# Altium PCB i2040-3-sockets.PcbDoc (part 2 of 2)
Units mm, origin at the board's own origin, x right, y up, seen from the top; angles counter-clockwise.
Board outline 210 x 90 mm, 2 copper layers (Top Layer, Bottom Layer), stack 1.575 mm thick; 146 components, 88 nets, 453 pads, 125 vias.
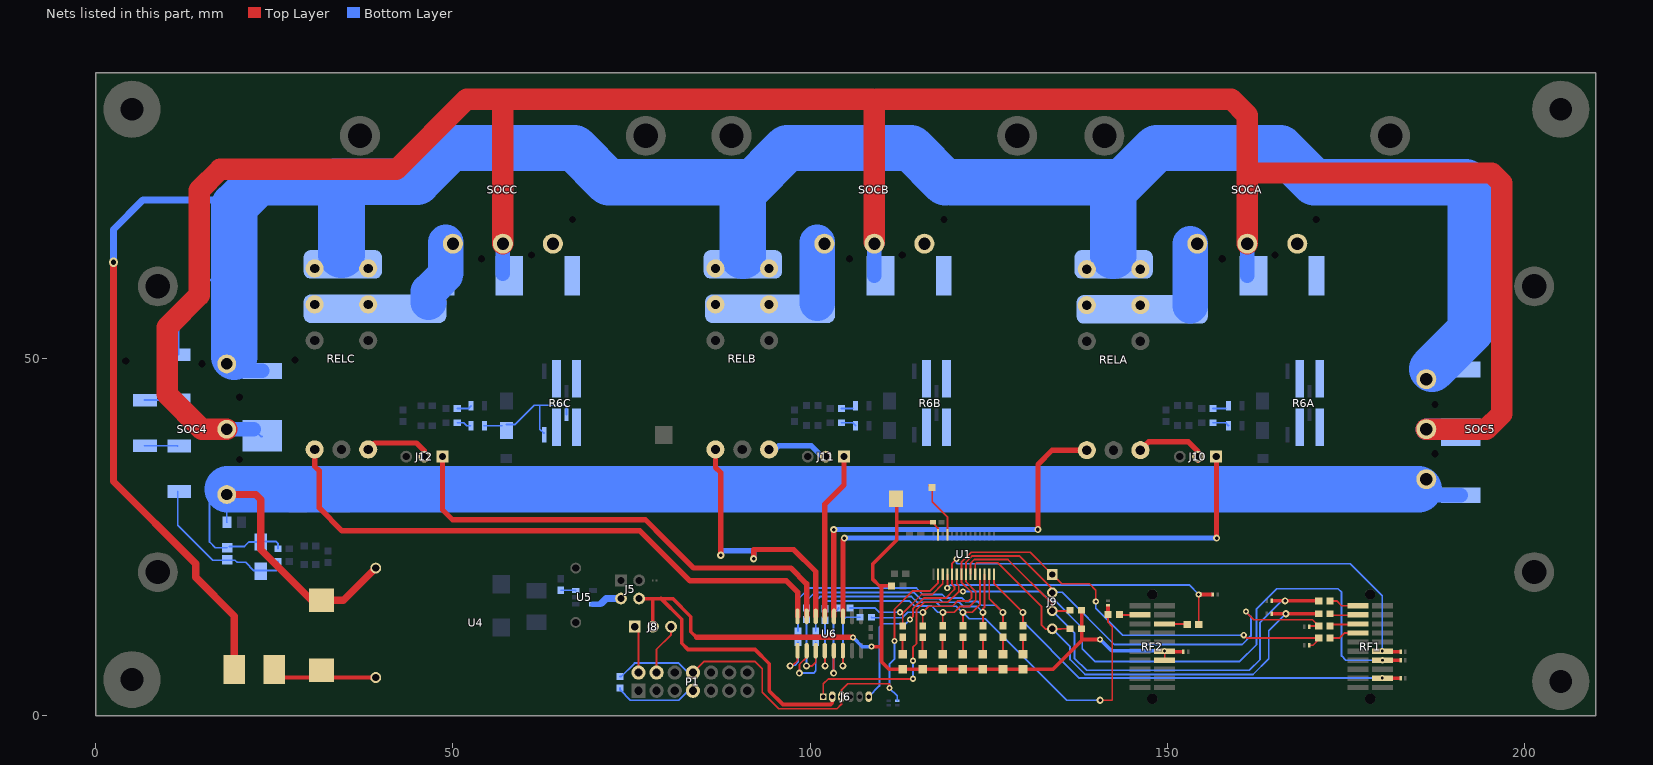
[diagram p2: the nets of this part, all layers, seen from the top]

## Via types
v1: diameter 1, hole 0.5, Top Layer to Bottom Layer, 44 vias
v2: diameter 0.864, hole 0.406, Top Layer to Bottom Layer, 40 vias
v3: diameter 1.27, hole 0.711, Top Layer to Bottom Layer, 40 vias
v4: diameter 0.864, hole 0.406, Top Layer to Bottom Layer, tented bottom, 1 vias

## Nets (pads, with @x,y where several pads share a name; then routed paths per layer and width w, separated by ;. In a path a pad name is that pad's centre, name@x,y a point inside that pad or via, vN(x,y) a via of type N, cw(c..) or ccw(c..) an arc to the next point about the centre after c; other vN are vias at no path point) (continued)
NetD1C_2: D1C.2 L1C.1 R6C.4 R6C.6 | length 17.4
  Bottom Layer w0.254: L1C.1@54.364,40.625 D1C.2@56.868,40.625 ; D1C.2@57.518,40.775 58.675,40.775 61.4,43.5 62.17,43.5 62.17,40.13 62.7,39.6 R6C.6@62.8,39.6 ; 62.2,43.5 65.7,43.5 65.9,43.3 R6C.4@65.9,42.15
NetD2A_1: D2A.1 D2B.1 D2C.1 D3A.1 D3B.1 D3C.1 D9.1 D10.1 D11.1 D12.2 SOC4.3 SOC5.3 SOCA.3 SOCB.3 SOCC.3 | length 355.5
  Top Layer w0.254: 108.638,86.344 109,85.982 109.362,86.344
  Top Layer w3: SOC4.3@18.35,40.132 14.868,40.132 10,45 10,54.413 14.5,58.913 14.5,73.6 17.4,76.5 42.1,76.5 51.944,86.344 108.638,86.344 ; SOCC.3@57,66.1 57,86.3 ; SOCB.3@109,66.278 109,85.982 ; 109.362,86.344 158.956,86.344 161.2,84.1 161.2,76 ; SOCA.3@161.2,66.1 161.2,76 ; SOC5.3@186.258,40.132 194.668,40.132 196.8,42.264 196.8,74.6 195.4,76 161.2,76
  Bottom Layer w0.254: D10.1@22.132,40.132 23.164,39.1 D9.1@23.3,39.1 ; D11.1@190.732,40.132 D11.1@191.1,40.5
  Bottom Layer w2: SOC4.3@18.35,40.132 D10.1@22.132,40.132 ; D3C.1@57,61.9 SOCC.3@57,66.1 ; D3B.1@109,61.6 SOCB.3@109,66.1 ; D3A.1@161.2,61.6 SOCA.3@161.2,66.1
  Bottom Layer w3: SOC5.3@186.258,40.132 D11.1@190.732,40.132
NetD2A_2: D2A.2 R6A.1 SOCA.2
NetD2B_2: D2B.2 R6B.1 SOCB.2
NetD2C_2: D2C.2 R6C.1 SOCC.2
NetD3A_2: D3A.2 pad.0@146.5,56.9 RELA.5 RELA.6 SOCA.1 | length 8.7
  Bottom Layer w5: pad.0@153.2,57.4 SOCA.1@153.2,66.1
NetD3B_2: D3B.2 pad.0@94.4,57 RELB.5 RELB.6 SOCB.1 | length 8.5
  Bottom Layer w5: pad.0@101,57.8 SOCB.1@101,66.3
NetD3C_2: D3C.2 pad.0@39.1,57 RELC.5 RELC.6 SOCC.1 | length 9.4
  Bottom Layer w5: pad.0@46.6,57.9 46.6,59.4 48.9,61.7 48.9,61.9 49,62 SOCC.1@49,66.3
NetD6_1: D6.1 FR.1 U4.2 | length 12.6
  Top Layer w0.254: FR.1@25,5.3 FR.1@25.076,5.376 ; D6.1@31.6,5.4 D6.1@31.624,5.376
  Top Layer w0.5: FR.1@25.076,5.376 D6.1@30,5.376 ; D6.1@31.624,5.376 U4.2@39.2,5.376
NetD6_2: D6.2 D8.1 D9.2 D12.1 R6A.2 R6B.2 R6C.2 R11.1 R15.1 R55.2 R56.2 R57.2 R58.2 SOC4.2 SOC5.2 U4.1 | length 228.7
  Top Layer w1: SOC4.2@18.35,30.992 22.408,30.992 23.1,30.3 23.1,23.3 31.2,15.2 31.2,15.8 D6.2@31.6,16.2 34.7,16.2 U4.1@39.2,20.7
  Bottom Layer w0.254: 15.95,31.092 15.95,24.35 16.75,23.55 R15.1@18.4,23.55 ; SOC4.2@18.35,30.992 18.35,27.134 R58.2@18.384,27.1 ; R15.1@18.74,23.716 20.816,23.716 21.45,24.35 D8.1@23.1,24.35 ; D8.1@23.195,24.416 23.199,24.42 25.262,24.402 25.507,24.153 R11.1@25.5,23.4 ; 185.2,31.2 185.5,30.9
  Bottom Layer w2: 184.9,30.9 D12.1@191.1,30.9
  Bottom Layer w6.5: SOC4.2@18.45,31.7 185.2,31.7
NetD8_2: D8.2 R10.1 R14.2 R15.2 | length 22.5
  Bottom Layer w0.254: R14.2@11.5,31.425 11.5,26.7 16.4,21.8 19.5,21.8 19.8,21.5 21,21.5 22.15,20.35 25.247,20.35 25.5,20.603 R10.1@25.5,21.6
NetD10_2: D10.2 D11.2 FR.2 pad.0@34.6,63.2 pad.0@90.6,63.2 pad.0@142.5,63.2 R1.1 RELA.7 RELA.8 RELB.7 RELB.8 RELC.7 RELC.8 SOC4.1 SOC5.1 | length 374.6
  Top Layer w1: v3@2.5,63.3 2.5,32.8 14,21.3 14,19.4 19.4,14 FR.2@19.4,5.3
  Bottom Layer w0.254: R1.1@11.6,50.575 11.6,56.55 17.85,62.8 19.4,62.8 ; SOC4.1@18.4,50.4 18.4,49.222 19.322,48.3 ; 34.4,73.8 34.4,74.8 ; 90.55,73.7 91,73.7 ; RELA.8@146.236,62.54 146.239,63.185 RELA.8@146.24,63.54
  Bottom Layer w1: v3(2.5,63.5) 2.5,68.1 6.6,72.2 18.35,72.2
  Bottom Layer w2: 19.322,48.3 D10.2@23.3,48.3
  Bottom Layer w5: 191.8,74.7 192.5,74
  Bottom Layer w6.5: 19.4,50.3 19.4,63 ; 19.4,63.6 19.4,71.4 22.7,74.7 33.5,74.7 ; 34.4,74.8 45,74.8 49.7,79.5 67,79.5 71.8,74.7 90.55,74.7 ; pad.0@90.55,64.4 90.55,73.7 ; 91,73.7 96.8,79.5 114.1,79.5 118.9,74.7 ; 119.9,74.7 142.45,74.7 ; pad.0@142.45,64.4 142.45,73.7 ; 142.7,73.7 148.5,79.5 165.8,79.5 170.6,74.7 191.8,74.7 ; 187.058,48.558 192.5,54 192.5,74
  Bottom Layer w6.6: 33.5,74.7 34.4,73.8 pad.0@34.4,64.6
NetJ5_3: J5.3 U5.5 | length 4.3
  Bottom Layer w0.75: U5.5@69.6,15.65 70.65,15.65 70.8,15.8
  Bottom Layer w1: 70.8,15.8 70.84,15.8 71.47,16.43 J5.3@73.53,16.43
NetJ6_1: J6.1 RF1.7 U1.20 U7.1 | length 118
  Top Layer w0.254: J6.1@101.85,2.7 101.85,4.485 102.535,5.17 114.4,5.17 v2(114.4,5.2) ; v2(114.4,7.728) 114.4,9.6 114.9,10.1 114.9,14.843 115.957,15.9 119.3,15.9 120.8,17.4 ; U1.20@120.525,19.825 120.525,18.5 120.8,18.225 120.8,17.4 ; v2(121.4,17.4) 120.8,17.4 ; v2(180.115,7.795) RF1.7@180.12,7.795
  Top Layer w0.5: RF1.7@180.12,7.8 U7.1@182.5,7.8
  Bottom Layer w0.254: v2(114.4,5.2) v2(114.4,7.728) ; v2(121.4,17.4) 132.233,17.4 133.453,16.18 134.22,16.18 138.088,12.312 138.088,9.412 139.9,7.6 160.1,7.6 162.5,10 162.5,15 165.3,17.8 173.9,17.8 174.4,17.3 174.4,8.4 175.005,7.795 v2(180.115,7.795)
NetJ6_3: J6.3 P1.8 R34.1 U1.16 U17.1 | length 69.9
  Top Layer w0.254: P1.8@83.6,6.07 85.13,7.6 92.3,7.6 93.3,6.6 93.3,3.3 95.6,1 103.77,1 104.39,1.62 J6.3@104.39,2.7 104.39,3.59 105.3,4.5 111.1,4.5 v2(111.1,3.9) ; v2(111.8,10.5) 111.8,14.9 114.4,17.5 116.8,17.5 117.925,18.625 U1.16@117.925,19.825
  Bottom Layer w0.254: R34.1@73.4,5.5 73.529,5.5 75.429,7.4 81.611,7.4 82.941,6.07 P1.8@83.6,6.07 ; v2(111.8,10.5) 111.8,7.924 111.1,7.225 v2(111.1,3.9) 112.2,2.8 U17.1@112.2,2.14
NetJ6_6: J6.6 RF1.9 U1.19 U15.1 | length 100.6
  Top Layer w0.254: v2(114,13.5) 114.4,13.9 114.4,15 115.9,16.5 119,16.5 120.2,17.7 120.2,18.1 119.875,18.425 U1.19@119.875,19.825 119.875,21.354 v2(120.5,21.979)
  Top Layer w0.5: v2(180.1,9.1) 180.2,9 U15.1@182.5,9
  Bottom Layer w0.254: J6.6@108.2,2.7 109.7,4.2 109.7,12.4 110.2,12.9 113.4,12.9 v2(114,13.5) ; v2(120.5,21.979) 120.5,21.4 120.6,21.3 175.597,21.3 180.1,16.798 v2(180.1,9.1)
NetJ8_1: J8.1 P1.2 | length 6.6
  Top Layer w0.254: J8.1@75.46,12.5 75.98,11.98 P1.2@75.98,6.07
NetJ8_3: J8.3 P1.4 | length 7.5
  Top Layer w0.254: P1.4@78.52,5.87 78.5,5.89 78.5,9.33 80.54,11.37 J8.3@80.54,12.5
NetJ9_1: J9.1 R3.1 R43.1 R49.2 U1.21 U9.1 | length 81.6
  Top Layer w0.254: R3.1@115.77,12.606 115.77,14.47 v1(115.8,14.5) 116.64,15.34 119.94,15.34 120.7,16.1 122.2,16.1 122.6,16.5 122.6,17.3 121.175,18.725 U1.21@121.175,19.825 121.175,21.493 122.582,22.9 130.8,22.9 J9.1@133.9,19.8 135.2,18.5 139.112,18.5 140,17.612 v2(140,16) ; v2(160.7,11.3) 161.1,10.9 R49.2@171.2,10.9 171.2,10.7 170.4,9.9 U9.1@169.84,9.9
  Bottom Layer w0.254: R43.1@108.6,13.8 108.662,13.738 112.916,13.738 113.678,14.5 v1(115.8,14.5) ; v2(140,16) 140,15.051 143.751,11.3 v2(160.7,11.3)
NetJ9_2: J9.2 R4.1 R44.1 R50.2 U1.22 U10.1 | length 93.6
  Top Layer w0.254: R4.1@118.57,12.617 v1@118.57,14.5 ; v1(118.6,14.5) 120.2,14.5 121.036,15.336 122.336,15.336 123.2,16.2 123.2,17.4 121.825,18.775 U1.22@121.825,19.825 121.825,21.497 122.728,22.4 129.3,22.4 133.9,17.8 J9.2@133.9,17.26 ; v2(161,14.6) 162.13,13.47 170.33,13.47 R50.2@171.2,12.6 169.94,12.6 U10.1@169.84,12.5
  Bottom Layer w0.254: R44.1@102.1,15 102.1,16 102.2,16.1 113.9,16.1 114.6,15.4 117,15.4 117.9,14.5 v1(118.6,14.5) ; J9.2@133.9,17.3 135.3,17.3 142.6,10 160.5,10 161.7,11.2 161.7,13.9 v2(161,14.6)
NetJ9_3: J9.3 R32.1 R52.2 U1.23 U13.1 | length 71
  Top Layer w0.254: U1.23@122.475,19.825 122.475,21.375 123,21.9 127.7,21.9 133.9,15.7 J9.3@133.9,14.72 ; J9.3@133.9,14.7 136.4,14.7 R32.1@136.4,14.8
  Top Layer w0.5: U13.1@164.74,16.1 v1(166.5,16.1) R52.2@171.2,16.1
  Bottom Layer w0.254: J9.3@133.9,14.72 137,11.62 137,8.1 138.7,6.4 161.5,6.4 163,7.9 163,13.1 166,16.1 v1(166.5,16.1)
NetJ9_4: J9.4 R33.1 R51.2 U1.24 U12.1 | length 69
  Top Layer w0.254: U1.24@123.125,19.825 123.125,21.268 123.3,21.443 126.257,21.443 132.4,15.3 132.4,12.7 132.92,12.18 J9.4@133.9,12.18 135.116,12.18 135.136,12.2 R33.1@136.4,12.2 ; U12.1@164.64,14.2 U12.1@164.74,14.3
  Top Layer w0.5: U12.1@164.74,14.3 v1(166.6,14.3) R51.2@171.2,14.3
  Bottom Layer w0.254: J9.4@133.9,12.18 136.4,9.68 136.4,7.9 138.5,5.8 162,5.8 164.2,8 164.2,11.9 v1(166.6,14.3)
NetJ10_1: J10.1 U6.11 | length 73.8
  Top Layer w0.254: J10.1@156.84,35.8 J10.1@156.9,35.74
  Top Layer w0.75: U6.11@104.603,13.929 v1@104.603,24.703 ; v1(156.9,24.9) J10.1@156.9,35.74
  Bottom Layer w0.75: v1(104.8,24.9) v1(156.9,24.9)
NetJ10_2: J10.2 RELA.2 | length 10.3
  Top Layer w0.75: RELA.2@146.236,37.2 147.39,38.354 152.946,38.354 154.3,37 J10.2@154.3,35.8
NetJ11_1: J11.1 U6.13 | length 23.5
  Top Layer w0.75: U6.13@102.063,13.929 102.063,29.663 104.74,32.34 J11.1@104.74,36.3
NetJ11_2: J11.2 RELB.2 | length 9
  Top Layer w1: RELB.2@94.258,37.3 RELB.2@94.558,37.6
  Bottom Layer w0.75: RELB.2@95.1,37.3 95.6,37.8 100.2,37.8 J11.2@101.95,36.05
  Bottom Layer w1: RELB.2@94.258,37.3 RELB.2@95.1,37.3
NetJ12_1: J12.1 U6.15 | length 67.3
  Top Layer w0.75: J12.1@48.54,36.3 48.54,28.86 49.94,27.46 76.94,27.46 79.7,24.7 83.7,20.7 97.3,20.7 99.523,18.477 U6.15@99.523,13.929
NetJ12_2: J12.2 RELC.2 | length 9.5
  Top Layer w0.75: RELC.2@38.15,37.3 39.05,38.2 44.9,38.2 46,37.1 J12.2@46,36.3
NetL1A_2: L1A.2 R9A.1 | length 2.3
  Bottom Layer w0.254: R9A.1@156.418,41.034 158.164,41.034 L1A.2@158.564,40.634
NetL1B_2: L1B.2 R9B.1 | length 2.1
  Bottom Layer w0.254: R9B.1@104.418,41.034 105.964,41.034 L1B.2@106.364,40.634
NetL1C_2: L1C.2 R9C.1 | length 2
  Bottom Layer w0.254: R9C.1@50.618,41.025 51.515,41.025 51.915,40.625 L1C.2@52.464,40.625
NetL2A_2: L2A.2 R8A.1 | length 1.7
  Bottom Layer w0.254: R8A.1@156.418,43.034 158.164,43.034
NetL2B_2: L2B.2 R8B.1 | length 1.5
  Bottom Layer w0.254: R8B.1@104.418,43.034 105.964,43.034
NetL2C_2: L2C.2 R8C.1 | length 2.1
  Bottom Layer w0.254: R8C.1@50.618,43.025 52.164,43.025 L2C.2@52.564,43.425
NetLED1_2: LED1.2 R2.2 | length 2.4
  Top Layer w0.254: LED1.2@112.957,8.651 112.957,10.942 112.97,10.956 R2.2@112.97,11.006
NetLED2_2: LED2.2 R3.2 | length 2.4
  Top Layer w0.254: LED2.2@115.757,8.651 115.757,10.942 115.77,10.956 R3.2@115.77,11.006
NetLED3_2: LED3.2 R4.2 | length 2.4
  Top Layer w0.254: LED3.2@118.557,8.662 118.557,10.953 118.57,10.967 R4.2@118.57,11.017
NetLED4_2: LED4.2 R5.2 | length 2.4
  Top Layer w0.254: LED4.2@121.386,8.662 121.386,10.953 121.4,10.967 R5.2@121.4,11.017
NetLED5_2: LED5.2 R7.2 | length 2.4
  Top Layer w0.254: LED5.2@124.186,8.662 124.186,10.953 124.2,10.967 R7.2@124.2,11.017
NetLED6_2: LED6.2 R12.2 | length 2.4
  Top Layer w0.254: LED6.2@127.005,8.662 127.005,10.953 R12.2@127.018,11.017
NetLED7_2: LED7.2 R17.2 | length 2.4
  Top Layer w0.254: LED7.2@129.805,8.662 129.818,8.676 R17.2@129.818,11.017
NetP1_7: P1.7 R34.2 | length 11.6
  Bottom Layer w0.254: R34.2@73.4,3.9 73.4,3.643 74.843,2.2 81.611,2.2 82.941,3.53 P1.7@83.6,3.53
NetR1_2: R1.2 R13.1 | length 4.8
  Bottom Layer w0.254: R13.1@6.8,44.175 6.85,44.225 R1.2@11.6,44.225
NetR2_1: R2.1 R46.1 U1.17 | length 17.7
  Top Layer w0.254: R2.1@112.97,12.606 112.97,14.37 115.6,17 117.1,17 118.575,18.475 U1.17@118.575,19.825
  Bottom Layer w0.254: R46.1@105.6,15.1 109.1,15.1 109.7,14.5 v2(112.6,14.5)
NetR5_1: R5.1 R47.1 R53.2 U1.25 U11.1 | length 74.4
  Top Layer w0.254: R5.1@121.4,12.617 v1(121.4,14.5) 122.7,14.5 123.775,15.575 U1.25@123.775,19.825 ; v1(140.6,2.2) 142.3,2.2 142.3,12.5 141.7,13.1 R53.2@141.7,14.2 ; U11.1@141.7,15.3 U11.1@141.7,15.46
  Top Layer w0.5: R53.2@141.7,14.2 U11.1@141.7,15.3
  Bottom Layer w0.254: R47.1@100.8,11.9 100.8,16.1 101.4,16.7 114.2,16.7 115,15.9 117.64,15.9 118.2,15.34 120.46,15.34 v1@121.35,14.45 ; v1(121.4,14.5) 122.3,13.6 124.5,13.6 135.9,2.2 v1(140.6,2.2)
NetR7_1: R7.1 R45.1 U1.26 | length 34.7
  Top Layer w0.254: R7.1@124.2,12.617 v1(124.2,14.492) 124.2,15 124.425,15.225 U1.26@124.425,19.825
  Bottom Layer w0.254: R45.1@99.5,15.1 99.5,16.1 100.693,17.293 114.507,17.293 115.4,16.4 118.1,16.4 118.6,15.9 120.9,15.9 121.47,15.33 123.37,15.33 v1@124.2,14.5
NetR12_1: R12.1 R48.1 U1.27 | length 43.2
  Top Layer w0.254: U1.27@125.075,19.825 125.075,16.425 v1(127,14.5) 127.018,14.482 R12.1@127.018,12.617
  Bottom Layer w0.254: R48.1@98.3,11.9 98.3,16.3 99.9,17.9 114.9,17.9 115.8,17 118.5,17 119,16.5 121.3,16.5 121.8,16 123.5,16 124,15.5 126,15.5 v1(127,14.5)
NetR13_2: R13.2 R14.1 | length 4.7
  Bottom Layer w0.254: R13.2@6.8,37.825 11.45,37.825 R14.1@11.5,37.775
NetR17_1: R17.1 RF1.3 U1.28 U8.1 | length 66.1
  Top Layer w0.254: U1.28@125.725,19.825 125.725,18.575 v1@129.7,14.6 ; v1@129.818,14.5 R17.1@129.818,12.617 129.883,12.617 R17.1@129.9,12.6
  Top Layer w0.5: RF1.3@180.129,5.3 U8.1@182.5,5.3
  Bottom Layer w0.254: v1@129.818,14.5 129.818,13.182 137.7,5.3 v2(180.1,5.3)
  other v1: 129.8,14.5
NetR31_2: R31.2 U1.11 | length 8
  Top Layer w0.254: R31.2@116.6,32.3 117.1,31.8 117.1,30 119.225,27.875 119.225,27.547 119.23,27.542 119.23,25.38 U1.11@119.225,25.375
NetR39_1: R39.1 U5.3 | length 2.1
  Bottom Layer w0.254: R39.1@65.1,17.6 67.15,17.6 U5.3@67.2,17.55
NetR43_2: R43.2 U6.6 | length 11.1
  Top Layer w0.254: v1(104.6,7) U6.6@104.6,9.125
  Bottom Layer w0.254: v1(104.6,7) 104.6,13.4 105,13.8 R43.2@107,13.8
NetR44_2: R44.2 U6.4 | length 8.5
  Top Layer w0.254: U6.4@102.063,9.129 102.1,9.092 v1(102.1,7)
  Bottom Layer w0.254: v1(102.1,7) R44.2@102.1,13.4
NetR45_2: R45.2 U6.3 | length 9.6
  Top Layer w0.254: v1(99.5,7) 100.3,7 100.793,7.493 U6.3@100.793,9.129
  Bottom Layer w0.254: v1(99.5,7) R45.2@99.5,13.5
NetR46_2: R46.2 U6.5 | length 12.5
  Top Layer w0.254: v1(103.3,6) 103.3,9.095 U6.5@103.333,9.129
  Bottom Layer w0.254: v1(103.3,6) 103.3,14.4 R46.2@104,15.1
NetR47_2: R47.2 U6.2 | length 10
  Top Layer w0.254: v1(98.5,6) 98.5,7.2 99.523,8.223 U6.2@99.523,9.129
  Bottom Layer w0.254: v1(98.5,6) 100.5,6 100.8,6.3 R47.2@100.8,10.3
NetR48_2: R48.2 U6.1 | length 6.8
  Top Layer w0.254: v1(97.2,7) 97.3,7.1 97.6,7.1 98.253,7.753 U6.1@98.253,9.129
  Bottom Layer w0.254: v1@97.2,7.1 97.9,7.1 98.3,7.5 R48.2@98.3,10.3
NetR49_1: R49.1 RF1.14 | length 4.2
  Top Layer w0.254: R49.1@172.8,10.9 174.1,10.9 174.8,11.6 176.68,11.6 RF1.14@176.685,11.605
NetR50_1: R50.1 RF1.16 | length 3.9
  Top Layer w0.254: R50.1@172.8,12.8 176.61,12.8 RF1.16@176.685,12.875
NetR51_1: R51.1 RF1.18 | length 3.9
  Top Layer w0.254: R51.1@172.8,14.1 176.64,14.1 RF1.18@176.685,14.145
NetR52_1: R52.1 RF1.20 | length 4.2
  Top Layer w0.254: R52.1@172.8,16.1 173.7,16.1 174.385,15.415 RF1.20@176.685,15.415
NetR53_1: R53.1 RF2.18 | length 2.9
  Top Layer w0.254: R53.1@143.3,14.2 143.355,14.145 RF2.18@146.205,14.145
NetR54_1: R54.1 U1.18 U16.1 | length 43.8
  Top Layer w0.254: v2@119.225,17.9 U1.18@119.225,19.825 ; R54.1@154.4,12.8 v2(154.4,17)
  Top Layer w0.5: v2(154.4,17) U16.1@156.2,17
  Bottom Layer w0.254: v2@119.225,17.9 119.665,18.34 153.059,18.34 v2(154.4,17)
  other v2: 119.2,17.9
NetR54_2: R54.2 RF2.15 | length 3.2
  Top Layer w0.254: RF2.15@149.635,12.875 152.8,12.875 R54.2@152.8,12.8
NetRELA_1: RELA.1 U6.12 | length 57.8
  Top Layer w0.254: v1@103.3,26.1 v1(103.317,26.083) 103.317,25.833 103.333,25.85 103.442,25.958 v1@103.5,26.017
  Top Layer w0.75: U6.12@103.333,13.929 103.333,25.85 v1@103.333,26.017 ; v1(131.9,26.1) 131.9,35.2 133.9,37.2 RELA.1@138.736,37.2
  Bottom Layer w0.75: v1@103.5,26.1 v1(131.9,26.1)
NetRELB_1: RELB.1 U6.14 | length 39.8
  Top Layer w0.254: 100.7,20.2 100.793,20.2
  Top Layer w0.75: RELB.1@86.758,37.3 86.758,34.804 87.5,34.062 v1(87.5,22.5) ; v1(92.1,22) 92.1,23.3 97.7,23.3 100.75,20.25 ; U6.14@100.793,13.929 100.793,20.2
  Bottom Layer w0.254: RELB.1@86.758,36.342 RELB.1@86.758,37.3
  Bottom Layer w0.75: v1(87.5,22.5) 87.5,23.1 91.9,23.1 92.1,22.9 v1(92.1,22)
NetRELC_1: RELC.1 U6.16 | length 83.7
  Top Layer w0.75: RELC.1@30.65,37.3 30.65,34.95 31.3,34.3 31.3,29.1 34.5,25.9 76.2,25.9 83.2,18.9 96.7,18.9 98.253,17.347 U6.16@98.253,13.929
VCC: C11.1 C19.1 J5.4 J6.2 J8.2 LED1.1 LED2.1 LED3.1 LED4.1 LED5.1 LED6.1 LED7.1 R16.1 R32.2 R33.2 RF2.7 RF2.9 U1.13 U14.1 | length 161
  Top Layer w0.254: C19.1@112.025,30.4 C19.1@112.123,30.302 ; C11.1@117.375,27.1 117.375,26.825 117.9,26.3 117.9,25.4 U1.13@117.925,25.375 ; LED3.1@118.546,6.551 LED3.1@118.557,6.562 ; 138,10.5 138,10.7 ; R33.2@138,12.2 R33.2@138.05,12.2 ; R32.2@138,14.8 R32.2@138.05,14.8 ; v2(149.6,9.1) RF2.9@149.635,9.065 ; RF2.7@149.635,7.795 RF2.9@149.635,9.065 ; RF2.9@149.7,9 RF2.9@149.635,9.065
  Top Layer w0.5: J5.4@76.07,16.43 78,16.43 ; J8.2@78,12.5 78,16.43 ; 79.135,16.436 82.032,13.538 82.032,10.164 82.907,9.302 92.298,9.302 94.3,7.3 94.3,3.5 96.2,1.6 102.9,1.6 103.12,1.82 J6.2@103.12,2.7 ; 84.1,11 83.3,11.8 83.3,13.9 80.77,16.43 78,16.43 ; v2(108.6,9.7) 110,9.7 ; 110,18.1 110,7.6 111.049,6.551 LED1.1@112.957,6.551 LED2.1@115.757,6.551 LED3.1@118.546,6.551 ; R16.1@111.4,18.2 109.7,18.2 108.8,19.1 108.8,21.313 112.123,24.636 C19.1@112.123,30.302 ; 112.123,27.1 C11.1@117.2,27.1 ; LED3.1@118.557,6.562 LED4.1@121.386,6.562 LED5.1@124.186,6.562 LED6.1@127.005,6.562 LED7.1@129.805,6.562 134.05,6.562 138,10.5 ; R33.2@138,12.2 138,10.7 v2(140.6,10.7) ; R33.2@138.05,12.2 R32.2@138.05,14.8 ; RF2.9@149.7,9 U14.1@152.1,9
  Top Layer w0.75: 84.1,11 v2(106,11)
  Top Layer w1: J5.4@76.07,16.43 J5.4@76.07,16.453
  Bottom Layer w0.5: v2(106,11) 107.3,9.7 v2(108.6,9.7) ; v2(140.6,10.7) 142.2,9.1 v2(149.6,9.1)
pads on no net: H1.1 H2.1 H3.1 H4.1 H6.0 Logo6.0 P1.3 P1.5 P1.6 P1.10 P1.11 P1.12 P1.13 P1.14 RELA.3 RELA.4 RELB.3 RELB.4 RELC.3 RELC.4 RF1. RF1.2 RF1.4 RF1.5 RF1.6 RF1.8 RF1.10 RF1.11 RF1.12 RF1.13 RF1.15 RF1.17 RF2. RF2.1 RF2.3 RF2.4 RF2.5 RF2.6 RF2.8 RF2.10 RF2.11 RF2.12 RF2.13 RF2.14 RF2.16 RF2.17 RF2.19 SOC4.MH1 SOC4.MH2 SOC5.MH1 SOC5.MH2 SOCA.MH1 SOCA.MH2 SOCB.MH1 SOCB.MH2 SOCC.MH1 SOCC.MH2 U5.4 U6.7 U6.10

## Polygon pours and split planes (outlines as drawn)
DGND on Bottom Layer "Bottom Layer-DGND" (solid, remove dead copper, pour order 14): 74,24.3 185,24.3 185,0.5 74,0.5 74,24.3
AGND on Bottom Layer "Bottom Layer-AGNDA" (solid, remove dead copper, pour order 13): 121.6,46.8 165.7,46.8 165.7,31 121.6,31 121.6,46.8
AGND on Bottom Layer "Bottom Layer-AGND2" (solid, remove dead copper, pour order 17): 132.5,31 20.1,31 20.1,14.6 132.5,14.6 132.5,31
AGND on Bottom Layer "Bottom Layer-AGNDA" (solid, remove dead copper, pour order 15): 62.2,46.8 40.9,46.8 40.9,31 62.2,31 62.2,46.8
AGND on Bottom Layer "Bottom Layer-AGNDB" (solid, remove dead copper, pour order 16): 69.6,46.8 113.8,46.8 113.8,31 69.6,31 69.6,46.8
DGND on Top Layer "Top Layer-DGND" (solid, remove dead copper, pour order 10): 74,18 185,18 185,0.5 74,0.5
AGND on Top Layer "Top Layer-AGND" (solid, remove dead copper, pour order 11): 174,48 174,18.288 40.9,18.288 40.9,48
AGND on Top Layer "Top Layer-AGND2" (solid, remove dead copper, pour order 12): 77.471,14.5 30.226,14.5 30,14.6 30,28.5 77.471,28.5

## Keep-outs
Keep-Out Layer:
  lines w0: -0.127,0 ccw(c0,0) 0,-0.127
  text ".Layer_Name" at 14.656,-21.806 h1.52

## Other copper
Top Layer:
  text ".Layer_Name" at 14.656,-21.806 h1.52
Bottom Layer:
  region net NetD6_2: 69.3,37.9 62.49,37.9 62.49,33.5 69.3,33.5
  region net NetD6_2: 121.11,37.9 114.3,37.9 114.3,33.5 121.11,33.5
  region net NetD6_2: 173.334,37.9 166.524,37.9 166.524,33.5 173.334,33.5
  region net NetD2A_2: 173.33,67.7 166.52,67.7 166.52,49.8 173.33,49.8
  region net NetD2B_2: 121.11,67.7 114.302,67.7 114.302,49.8 121.11,49.8
  region net NetD2C_2: 69.3,67.7 62.5,67.7 62.5,49.8 69.3,49.8
  text ".Layer_Name" at 14.656,-21.806 h1.52
Multi-Layer:
  text "TIDM-3OUTSMTSTRP" at 178.5,-7.1 h2.02

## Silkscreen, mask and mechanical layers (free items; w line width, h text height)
Top Overlay:
  text "©" at 188.6,87.4 h2.67
  text ".CopyrightYear" at 191.4,87.4 h1.52
  text "TI" at 198.41,87.4 h1.52
  text "AC 85-250V 15A Max" at 1.9,74.9 h2
  text "MSP430i2040 Multi-output Embedded Meter EVM" at 97.9,51.4 h1.8
  text "J10, J11, J12" at 56.4,32.8 h2
  text "CAUTION" at 82.7,31.8 h2
  text "1-2 Latched Relay" at 56.4,30.9 h2
  text "Debugging Interfaces" at 82.7,29.7 h2
  text "2-3 Non-Latched" at 56.4,28.9 h2
  text "ARE NOT ISOLATED" at 82.7,27.4 h2
  text "Disconnect Debugger" at 82.7,25.3 h2
  text "Before Applying Line" at 82.7,23 h2
  text "Voltage to the Board" at 82.7,20.7 h2
  text "GND" at 77.9,18.5 h1.02
  text "VCC" at 77.9,15.9 h1.02
  text "FET 1-2, EXT 2-3" at 71.7,10.2 h0.8
  text "CAUTION" at 152,4.7 h2
  text "Serial Interfaces" at 152,2.6 h2
  text "ARE NOT ISOLATED" at 152,0.6 h2
  text ".Layer_Name" at 14.656,-21.806 h1.52
Bottom Overlay:
  text ".Layer_Name" at 14.656,-21.806 h1.52
Top Paste:
  text ".Layer_Name" at 14.656,-21.806 h1.52
Bottom Paste:
  text ".Layer_Name" at 14.656,-21.806 h1.52
Top Solder:
  text ".Layer_Name" at 14.656,-21.806 h1.52
  text ".Layer_Name" at 14.656,-21.806 h1.52
Bottom Solder:
  text ".Layer_Name" at 14.656,-21.806 h1.52
Drill Guide:
  text ".Layer_Name" at 14.656,-21.806 h1.52
M1 Board Outline:
  the board outline again, w0.254
  text ".Layer_Name" at 14.656,-21.806 h1.52
M2 Board Dimensions:
  rectangle: -0.013,-7.252 3.162,-4.077
  rectangle: 3.162,-10.427 12.687,-7.252
  lines w0.178: -0.013,-7.252 25.387,-7.252 ; 3.162,-10.427 3.162,-4.077 ; 6.337,-10.427 6.337,-4.077 ; 12.687,-10.427 12.687,-4.077 ; 19.037,-10.427 19.037,-4.077 ; -0.013,-10.427 25.387,-10.427 25.387,-4.077 -0.013,-4.077 -0.013,-10.427
  lines w0.254: -0.013,-12.078 -0.013,-11.57 ; 1.511,-12.332 -0.013,-11.824 ; 1.511,-11.316 -0.013,-11.824 ; 6.187,-11.824 -0.013,-11.824 ; 19.188,-11.824 25.387,-11.824 ; 23.863,-12.332 25.387,-11.824 ; 23.863,-11.316 25.387,-11.824 ; 25.387,-12.078 25.387,-11.57
  text "25.4 (mm)" at 6.441,-12.738 h1.52
  text ".Layer_Name" at 14.656,-21.806 h1.52
M3 3D STEP Top:
  text ".Layer_Name" at 14.656,-21.806 h1.52
M4 3D STEP Bottom:
  text ".Layer_Name" at 14.656,-21.806 h1.52
M5 Assembly Top:
  lines w0.254: -7.417,-23.626 160.223,-23.626 ; -7.417,-18.462 160.274,-18.462 ; -7.417,-13.297 -7.417,-28.791 94.31,-28.791 160.274,-28.791 160.274,-13.297 -7.404,-13.297 -7.404,-28.791 32.614,-28.791 ; 55.194,-28.791 55.194,-13.297 ; 87.376,-18.462 87.376,-13.297 ; 108.712,-18.462 108.712,-13.297 ; 124.511,-28.956 124.511,-23.804
  text "COMPONENTS MARKED 'DNP' SHOULD NOT BE POPULATED." at 29.299,-8.09 h1.52
  text "ASSEMBLY VARIANT:" at 29.286,-11.024 h1.52
  text ".VariantName" at 55.601,-11.024 h1.52
  text "PCB VIEWED FROM TOP SIDE" at -5.804,-16.654 h1.52
  text "BOARD #:" at 57.099,-16.654 h1.52
  text ".PRJ_Number" at 70.955,-16.654 h1.52
  text "REV:" at 92.405,-16.654 h1.52
  text ".PCB_Rev" at 99.809,-16.654 h1.52
  text "SVN REV:" at 113.69,-16.654 h1.52
  text ".VersionControl_RevNumber" at 126.543,-16.654 h1.52
  text "IGNORE ->" at -5.804,-21.806 h1.52
  text "PLOT NAME =" at -5.804,-27.034 h1.52
  text ".plot_File_Name" at 14.656,-27.034 h1.52
  text "GENERATED    :" at 57.15,-27.034 h1.52
  text ".Print_Date" at 79.235,-27.034 h1.52
  text ".Print_Time" at 97.752,-27.034 h1.52
  text "TEXAS INSTRUMENTS" at 129.87,-27.034 h1.52
M6 Assembly Bottom:
  lines w0.254: -7.429,-18.474 160.261,-18.474 ; -7.379,-23.639 160.261,-23.639 ; 28.334,-28.969 28.334,-23.817 ; 44.133,-18.474 44.133,-13.31 ; 65.468,-18.474 65.468,-13.31 ; 97.65,-28.804 97.65,-13.31 ; 120.231,-28.804 160.249,-28.804 160.249,-13.31 -7.429,-13.31 -7.429,-28.804 58.534,-28.804 160.261,-28.804 160.261,-13.31
  text "COMPONENTS MARKED 'DNP' SHOULD NOT BE POPULATED." at 154.991,-8.077 h1.52
  text ".VariantName" at 128.473,-11.024 h1.52
  text "ASSEMBLY VARIANT:" at 154.864,-11.024 h1.52
  text ".VersionControl_RevNumber" at 26.302,-16.667 h1.52
  text "SVN REV:" at 39.154,-16.667 h1.52
  text ".PCB_Rev" at 53.035,-16.667 h1.52
  text "REV:" at 60.439,-16.667 h1.52
  text ".PRJ_Number" at 81.89,-16.667 h1.52
  text "BOARD #:" at 95.745,-16.667 h1.52
  text "PCB VIEWED FROM BOTTOM SIDE" at 158.648,-16.667 h1.52
  text "IGNORE ->" at 64.715,-21.806 h1.52
  text "TEXAS INSTRUMENTS" at 22.974,-27.047 h1.52
  text ".Print_Time" at 55.093,-27.047 h1.52
  text ".Print_Date" at 73.609,-27.047 h1.52
  text "GENERATED    :" at 95.694,-27.047 h1.52
  text ".plot_File_Name" at 138.189,-27.047 h1.52
  text "PLOT NAME =" at 158.648,-27.047 h1.52
M9 Title Sheet:
  drawing of 57 lines, arcs and shapes, not listed
  text "B" at 458.356,255.079 h1.78
  text "1" at 18.792,204.127 h1.78
  text "2" at 82.182,204.127 h1.78
  text "3" at 145.411,204.127 h1.78
  text "4" at 209.08,204.127 h1.78
  text "5" at 272.555,204.127 h1.78
  text "6" at 336.182,204.127 h1.78
  text "A" at -10.579,175.095 h1.78
  text "A" at 365.341,175.095 h1.78
  text "B" at -10.579,114.643 h1.78
  text "C" at -10.579,54.318 h1.78
  text "C" at 365.341,54.318 h1.78
  text "PROJECT TITLE:" at 288.125,7.048 h1.14
  text ".PRJ_Title" at 289.395,3.662 h1.78
  text "DESIGNED FOR:" at 288.125,-0.597 h1.14
  text ".PRJ_Customer" at 289.395,-4.153 h1.78
  text "D" at -10.579,-5.88 h1.78
  text "D" at 365.341,-5.88 h1.78
  text "FILE NAME:" at 288.125,-8.217 h1.14
  text ".PCB_File_Name_No_Path" at 289.395,-11.265 h1.78
  text "Texas Instruments (TI) and/or its licensors do not warrant the accuracy or completeness of this specification" at 161.9,-15.376 h1.14
  text "ENGINEER:" at 288.125,-15.583 h1.14
  text "LAYOUT BY:" at 326.352,-15.583 h1.14
  text "or any information contained therein. TI and/or its licensors do not warrant that this design will meet" at 160.757,-18.237 h1.14
  text ".PRJ_Engineer" at 289.395,-19.52 h1.78
  text ".PCB_Layout" at 327.635,-19.52 h1.78
  text "the specifications, will be suitable for your application or fit for any particular purpose, or will operate in" at 160.757,-21.099 h1.14
  text ".Layer_Name" at 14.656,-21.806 h1.52
  text "ALTIUM DESIGNER VERSION:" at 326.352,-23.457 h1.14
  text "an implementation. TI and/or its licensors do not warrant that the design is production worthy. You should" at 160.757,-23.961 h1.14
  text "completely validate and test your design implementation to confirm the system functionality for your application." at 161.9,-26.822 h1.14
  text ".print_Scale" at 289.395,-26.843 h1.78
  text ".Application_BuildNumber" at 327.635,-26.843 h1.78
  text "1" at 18.792,-32.093 h1.78
  text "2" at 82.182,-32.093 h1.78
  text "3" at 145.411,-32.093 h1.78
  text "4" at 209.08,-32.093 h1.78
  text "5" at 272.555,-32.093 h1.78
  text "6" at 336.182,-32.093 h1.78
M10 Fab Notes:
  drawing of 212 lines, arcs and shapes, not listed
  text "DESIGN INFORMATION" at 314.478,172.974 h1.52
  text "(REFER ALSO ARRAY/PANEL PROFILING INFORMATION)" at 305.294,168.866 h1.52
  text "BOARD SIZE" at 287.87,168.758 h1.52
  text "3450MIL" at 299.613,165.511 h1.52
  text "X" at 312.457,165.511 h1.52
  text "4950MIL" at 318.333,165.511 h1.52
  text "Number of Layers :" at 298.106,160.503 h1.52
  text "2" at 325.914,160.249 h1.52
  text "MIN. TRACK WIDTH:" at 298.106,156.972 h1.52
  text "8" at 325.951,156.972 h1.52
  text "MIL" at 329.881,156.972 h1.52
  text "MIN. CLEARANCE:" at 297.721,153.756 h1.52
  text "8" at 325.565,153.756 h1.52
  text "MIL" at 329.496,153.756 h1.52
  text "MIN. VIA PAD SIZE:" at 297.721,150.403 h1.52
  text "24" at 324.804,150.403 h1.52
  text "MIL" at 329.496,150.403 h1.52
  text "0.05mm (2MIL)" at 315.374,146.804 h1.52
  text "MINIMUM ANNULAR RING" at 289.358,146.695 h1.52
  text "EXTERNAL" at 333.357,146.695 h1.52
  text "PER" at 294.438,143.697 h1.52
  text "IPC-D-275 CLASS 2 LEVEL C" at 300.026,143.697 h1.52
  text "MIL, HOLES" at 337.827,140.845 h1.52
  text "+/-" at 327.859,140.827 h1.52
  text "+/-" at 349.551,140.827 h1.52
  text "REGISTRATION TOLERANCES:" at 289.358,140.7 h1.52
  text "METAL" at 319.833,140.7 h1.52
  text "5" at 334.468,140.7 h1.52
  text "3" at 355.626,140.7 h1.52
  text "MIL" at 358.579,140.7 h1.52
  text "MATERIAL:" at 287.459,135.38 h1.52
  text "FR-4 High Tg" at 312.515,131.815 h1.52
  text "FR-408" at 298.153,131.598 h1.52
  text "X" at 308.617,131.598 h1.52
  text "OTHER" at 335.948,131.598 h1.52
  text "62 MIL (1.6mm) +/-10%" at 306.283,127.465 h1.52
  text "THICKNESS:" at 289.358,127.356 h1.52
  text "X" at 303.028,127.356 h1.52
  text "OTHER" at 338.92,127.356 h1.52
  text "TOLERANCE:" at 289.358,123.343 h1.52
  text "X" at 310.677,123.343 h1.52
  text "ANSI IPC-6012 TYPE 3 CLASS 2" at 315.425,123.343 h1.52
  text "OTHER +/-" at 315.425,119.38 h1.52
  text "BOW & TWIST:" at 289.358,115.393 h1.52
  text "X" at 310.677,115.393 h1.52
  text "ANSI IPC-6012 TYPE 3 CLASS 2" at 315.425,115.393 h1.52
  text "OTHER +/-" at 315.425,111.367 h1.52
  text "COPPER THICKNESS (FINISHED):" at 287.459,107.925 h1.52
  text "1.4MIL (1oz)" at 309.811,104.046 h1.52
  text "2MIL (1.4oz)" at 329.293,104.046 h1.52
  text "2.8MIL (2oz)" at 347.759,104.046 h1.52
  text "OUTER:" at 296.527,103.937 h1.52
  text "X" at 306.548,103.921 h1.52
  text "N/A" at 347.747,100.067 h1.52
  text "1.4MIL (1oz)" at 309.811,100.058 h1.52
  text "2.8MIL (2oz)" at 329.293,100.058 h1.52
  text "INNER SIGNAL:" at 289.184,99.949 h1.52
  text "X" at 306.585,99.949 h1.52
  text "DRILLING:" at 287.459,96.419 h1.52
  text "REFERENCE:" at 289.358,93.447 h1.52
  text "X" at 305.823,93.447 h1.52
  text "AS SHOWN" at 310.573,93.447 h1.52
  text "X" at 328.709,93.447 h1.52
  text "NC_DRILL FILES" at 332.189,93.447 h1.52
  text "PTH MIN COPPER THICKNESS:" at 289.358,89.434 h1.52
  text "X" at 323.654,89.434 h1.52
  text "1MIL" at 327.134,89.434 h1.52
  text "OTHER" at 339.758,89.434 h1.52
  text "BOARD FINISH:" at 287.459,85.395 h1.52
  text "SILKSCREEN:" at 291.402,82.398 h1.52
  text "X" at 315.501,82.398 h1.52
  text "TOP" at 318.701,82.398 h1.52
  text "X" at 328.455,82.398 h1.52
  text "BOTTOM" at 331.681,82.398 h1.52
  text "SILKSCREEN COLOR:" at 291.402,78.156 h1.52
  text "X" at 315.474,78.156 h1.52
  text "WHITE" at 318.701,78.156 h1.52
  text "OTHER" at 331.681,78.156 h1.52
  text "SOLDER RESIST COLOR:" at 291.402,73.838 h1.52
  text "X" at 305.823,69.795 h1.52
  text "GREEN" at 309.049,69.795 h1.52
  text "BLUE" at 324.061,69.795 h1.52
  text "OTHER" at 337.726,69.795 h1.52
  text "IMMERSION GOLD (ENIG)" at 314.409,65.006 h1.52
  text "ENEPIG" at 348.382,64.923 h1.52
  text "SURFACE FINISH:" at 287.459,64.897 h1.52
  text "X" at 309.66,64.897 h1.52
  text "IMM. TIN/SILVER OR EQUIV" at 296.215,60.773 h1.52
  text "OTHER" at 332.574,60.773 h1.52
  text "ARRAY/PANEL:" at 287.844,56.226 h1.52
  text "CUT AND TRIM PER MECH LAYER 1" at 314.794,56.118 h1.52
  text "N.C. ROUTE" at 314.794,52.264 h1.52
  text "X" at 332.04,52.264 h1.52
  text "V. SCORE" at 336.79,52.264 h1.52
  text "CERTIFICATION:" at 287.844,48.784 h1.52
  text "MATERIALS AND WORKMANSHIP FOR ALL PCBS" at 306.259,48.784 h1.52
  text "TO MEET OR EXCEED THE REQUIREMENTS OF:" at 306.259,46.295 h1.52
  text "X" at 296.773,42.828 h1.52
  text "ANSI IPC-A-600F CLASS ->" at 300.303,42.828 h1.52
  text "X" at 341.935,42.828 h1.52
  text "2" at 344.956,42.828 h1.52
  text "1" at 336.955,42.79 h1.52
  text "3" at 353.948,42.79 h1.52
  text "X" at 296.825,38.777 h1.52
  text "UL 94V-0" at 300.303,38.777 h1.52
  text "X" at 317.45,38.777 h1.52
  text "RoHS" at 320.928,38.777 h1.52
  text "OTHER" at 337.296,38.777 h1.52
  text "PER ORDER" at 347.381,38.777 h1.52
  text "ADDITIONAL REQUIREMENTS:" at 287.844,35.195 h1.52
  text "MICROSECTION:" at 289.744,32.274 h1.52
  text "YES" at 312.749,32.274 h1.52
  text "REQUIRED" at 334.631,28.308 h1.52
  text "BARE BOARD ELEC. TEST:" at 289.744,28.236 h1.52
  text "NONE" at 322.909,28.236 h1.52
  text "X" at 331.405,28.236 h1.52
  text "PER ORDER" at 349.668,28.236 h1.52
  text "MANUFACTURER'S UL:" at 289.744,24.248 h1.52
  text "RAIL" at 319.353,24.139 h1.52
  text "METAL" at 331.845,24.139 h1.52
  text "X" at 341.376,24.13 h1.52
  text "SILK" at 344.842,24.139 h1.52
  text ".Layer_Name" at 14.656,-21.806 h1.52
M11 Gerber Information:
  lines w0.254: -7.417,-23.626 160.223,-23.626 ; -7.417,-18.462 160.274,-18.462 ; -7.417,-13.297 -7.417,-28.791 94.31,-28.791 160.274,-28.791 160.274,-13.297 -7.404,-13.297 -7.404,-28.791 32.614,-28.791 ; 55.194,-28.791 55.194,-13.297 ; 87.376,-18.462 87.376,-13.297 ; 108.712,-18.462 108.712,-13.297 ; 124.511,-28.956 124.511,-23.804
  text "ALL ARTWORK VIEWED FROM TOP SIDE" at -5.804,-16.654 h1.52
  text "BOARD #:" at 57.099,-16.654 h1.52
  text ".PRJ_Number" at 70.955,-16.654 h1.52
  text "REV:" at 92.405,-16.654 h1.52
  text ".PCB_Rev" at 99.809,-16.654 h1.52
  text "SVN REV:" at 113.69,-16.654 h1.52
  text ".VersionControl_RevNumber" at 126.543,-16.654 h1.52
  text "LAYER NAME =" at -5.804,-21.806 h1.52
  text "PLOT NAME =" at -5.804,-27.034 h1.52
  text ".plot_File_Name" at 14.656,-27.034 h1.52
  text "GENERATED    :" at 57.15,-27.034 h1.52
  text ".Print_Date" at 79.235,-27.034 h1.52
  text ".Print_Time" at 97.752,-27.034 h1.52
  text "TEXAS INSTRUMENTS" at 129.87,-27.034 h1.52
M12 Stackup:
  lines w0.152: 288.544,189.484 353.314,189.484 ; 288.544,192.136 353.314,192.136 ; 287.02,177.165 ccw(c287.884,177.165) 287.884,176.301 353.974,176.301 ccw(c353.974,177.165) 354.838,177.165 354.838,195.097 ccw(c353.974,195.097) 353.974,195.961 287.884,195.961 ccw(c287.884,195.097) 287.02,195.097 287.02,177.165
  text "The Stackup Legend below this is static." at 294.78,200.012 h1.52
  text "If you change the stackup, update the Legend." at 295.034,197.726 h1.52
  text "Layer Stack Up Detail for: Ref_Design.PcbDoc" at 288.544,192.966 h1.45
  text "Layer" at 288.544,191.145 h0.61
  text "Gerber" at 311.298,191.145 h0.61
  text "Copper" at 325.611,191.145 h0.61
  text "Dielectric" at 340.92,191.145 h0.61
  text "Name" at 288.544,189.926 h0.61
  text "Document" at 311.298,189.926 h0.61
  text "Thickness" at 325.611,189.926 h0.61
  text "Material" at 340.92,189.926 h0.61
  text "Top Solder Mask" at 288.544,187.565 h0.86
  text "(.GTS)" at 311.298,187.565 h0.86
  text "Solder Resist" at 340.92,187.565 h0.86
  text "Top Layer" at 288.544,185.107 h0.86
  text "(.GTL)" at 311.298,185.107 h0.86
  text "1.4mil" at 325.611,185.107 h0.86
  text "FR-4" at 340.92,183.879 h0.86
  text "Bottom Layer" at 288.544,182.65 h0.86
  text "(.GBL)" at 311.298,182.65 h0.86
  text "1.4mil" at 325.611,182.65 h0.86
  text "Bottom Solder Mask" at 288.544,180.192 h0.86
  text "(.GBS)" at 311.298,180.192 h0.86
  text "Solder Resist" at 340.92,180.192 h0.86
  text ".Layer_Name" at 14.656,-21.806 h1.52
M13 Component Bodies Top:
  text ".Layer_Name" at 14.656,-21.806 h1.52
M14 Component Bodies Bottom:
  text ".Layer_Name" at 14.656,-21.806 h1.52
M15 Courtyards Top:
  text ".Layer_Name" at 14.656,-21.806 h1.52
M16 Courtyards Bottom:
  text ".Layer_Name" at 14.656,-21.806 h1.52
Drill Drawing:
  text ".legend" at 273.152,226.136 h1.52
  text "Drill Table" at 273.152,223.85 h1.52
  text ".Layer_Name" at 14.656,-21.806 h1.52

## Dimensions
-4.5,90 to 210,0 on M2 Board Dimensions
210,8.9 to 0,90 on M2 Board Dimensions
85.4,-12.2 to 79.4,-15.3 on M2 Board Dimensions
48.9,-17 to 42.9,-16.3 on M2 Board Dimensions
